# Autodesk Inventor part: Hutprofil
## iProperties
Created: 2008-10
Part Number: Hutprofil
Document SubType Name: Blech
Designer: EH
Mass: 267.88 g
Surface Area: 1835.13 cm^2
Volume: 267.88 cm^3
Density: 1 g/cm^3
Author: EH
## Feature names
1. Erhebung2
2. Spiegeln1 [Mirror]
3. Grobblech1
4. Biegung1
